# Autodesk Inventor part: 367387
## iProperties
Created: 2006-07
Part Number: 367387
Material: 8.8 vz
Description: Sechskantschraube
Vendor: Autodesk Inc.
Document SubType Name: Modeling
Standard: DIN 931-1
Designer: I.Baliuc
Standards Organization: DIN
Language: de-DE
Size Designation: M10 x 45
Categories: <MemberInstance Version="R10.0.0"><Categories><Category DisplayName="Schrauben" InternalName="e4da775c-781d-43d5-af7c-5136215cf5a6" Mnemonic="FSTN"><Category Di
Density: 7.85 g/cm^3
Mass: 39.9 g
Surface Area: 22.5548 cm^2
Volume: 5.0828 cm^3
Abmessung: M10 x 45
Author: T.Messerschmitt
Comments: DIN 931-1 - M10 x 45
Revision Number: 367387
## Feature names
1. Körper [Revolution]
2. Kopf [Extrusion]
3. Fase1 [Revolution]
4. Fase2 [Chamfer]
